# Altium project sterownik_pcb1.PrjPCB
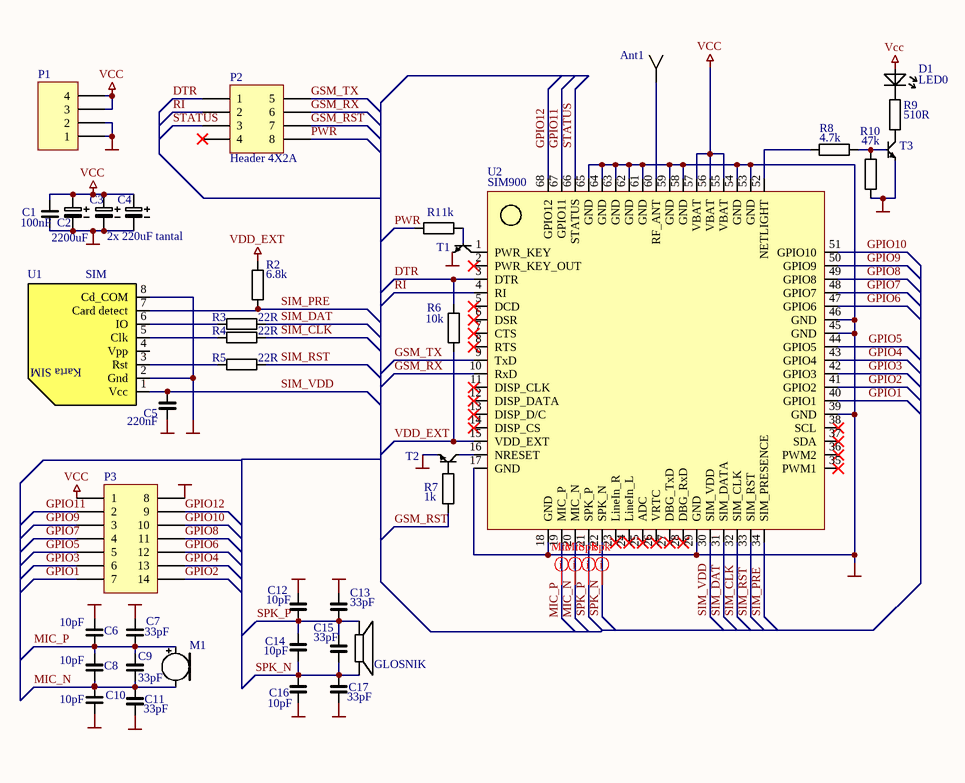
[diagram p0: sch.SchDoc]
1 sheet, 39 parts. Net scope: global (net labels, ports and power ports of the same name join across sheets).
Board file: modul_gsm.PcbDoc

## Sheet sch.SchDoc
size A4

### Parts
Ant1  Antena  [sma]  (value not drawn)
C1  100nF  [0805]
C2  2200uF  [CAPR5-4X5]
C3  2x 220uF tantal  [smd-d]
C4  CAP2  [smd-d]  (value not drawn)
C5  220nF  [0805]
C6  10pF  [0805]
C7  33pF  [0805]
C8  10pF  [0805]
C9  33pF  [0805]
C10  10pF  [0805]
C11  33pF  [0805]
C12  10pF  [0805]
C13  33pF  [0805]
C14  10pF  [0805]
C15  33pF  [0805]
C16  10pF  [0805]
C17  33pF  [0805]
D1  LED0  [led_0805]
M1  ELEKTRET  [ELEKTRET]  (value not drawn)
P1  Header 4  [HDR1X4]  (value not drawn)
P2  Header 4X2A  [HDR2X4_CEN]
P3  Header 7X2A  [HDR2X7_CEN]  (value not drawn)
R1  1k  [1206]
R2  6.8k  [1206]
R3  22R  [1206]
R4  22R  [1206]
R5  22R  [1206]
R6  10k  [1206]
R7  1k  [1206]
R8  4.7k  [1206]
R9  510R  [1206]
R10  47k  [1206]
T1  BC547B  [sot-23 rk]  (value not drawn)
T2  BC547B  [sot-23 rk]  (value not drawn)
T3  BC547B  [sot-23 rk]  (value not drawn)
U1  SIM  [simcard]
U2  SIM900  [SIM900]
  GLOSNIK  [hdr1x2]

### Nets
Gnd: Ant1.2 Ant1.3 Ant1.4 Ant1.5 C1.2 C2.2 C3.2 C4.2 C5.2 C6.1 C7.1 C10.2 C11.2 C12.1 C13.1 C16.2 C17.2 P1.1 P1.2 P3.8 R10.1(TOP) T1.1 T2.1 T3.1 U1.2(Gnd) U1.8(Cd_COM) U2.17(GND) U2.18(GND) U2.29(GND) U2.39(GND) U2.45(GND) U2.46(GND) U2.53(GND) U2.54(GND) U2.58(GND) U2.59(GND) U2.61(GND) U2.62(GND) U2.63(GND) U2.64(GND) U2.65(GND)
Vcc: C1.1 C2.1 C3.1 C4.1 D1.1(K) P1.3 P1.4 P3.1 U2.55(VBAT) U2.56(VBAT) U2.57(VBAT)
VDD_EXT: R2.1(TOP) R6.1(TOP) U2.15(VDD_EXT)
DTR: P2.1 R6.2(BOT) U2.3(DTR)
GPIO1: P3.7 U2.40(GPIO1)
GPIO2: P3.14 U2.41(GPIO2)
GPIO3: P3.6 U2.42(GPIO3)
GPIO4: P3.13 U2.43(GPIO4)
GPIO5: P3.5 U2.44(GPIO5)
GPIO6: P3.12 U2.47(GPIO6)
GPIO7: P3.4 U2.48(GPIO7)
GPIO8: P3.11 U2.49(GPIO8)
GPIO9: P3.3 U2.50(GPIO9)
GPIO10: P3.10 U2.51(GPIO10)
GPIO11: P3.2 U2.67(GPIO11)
GPIO12: P3.9 U2.68(GPIO12)
GSM_RST: P2.7 R7.2(BOT)
GSM_RX: P2.6 U2.10(RxD)
GSM_TX: P2.5 U2.9(TxD)
MIC_N: C8.2 C9.2 C10.1 C11.1 M1.2 U2.20(MIC_N)
MIC_P: C6.2 C7.2 C8.1 C9.1 M1.1 U2.19(MIC_P)
PWR: P2.8 R1.2(BOT)
RI: P2.2 U2.4(RI)
SIM_CLK: R4.1(TOP) U2.32(SIM_CLK)
SIM_DAT: R3.1(TOP) U2.31(SIM_DATA)
SIM_PRE: R2.2(BOT) U1.7(Card_detect) U2.34(SIM_PRESENCE)
SIM_RST: R5.1(TOP) U2.33(SIM_RST)
SIM_VDD: C5.1 U1.1(Vcc) U2.30(SIM_VDD)
SPK_N: C14.2 C15.2 C16.1 C17.1 U2.22(SPK_N) .2(B)
SPK_P: C12.2 C13.2 C14.1 C15.1 U2.21(SPK_P) .1(A)
STATUS: P2.3 U2.66(STATUS)
NetAnt1_1: Ant1.1 U2.60(RF_ANT)
NetD1_2: D1.2(A) R9.2(BOT)
NetR1_1: R1.1(TOP) T1.2
NetR3_2: R3.2(BOT) U1.6(IO)
NetR4_2: R4.2(BOT) U1.5(Clk)
NetR5_2: R5.2(BOT) U1.3(Rst)
NetR7_1: R7.1(TOP) T2.2
NetR8_1: R8.1(TOP) R10.2(BOT) T3.2
NetR8_2: R8.2(BOT) U2.52(NETLIGHT)
NetR9_1: R9.1(TOP) T3.3
NetT1_3: T1.3 U2.1(PWR_KEY)
NetT2_3: T2.3 U2.16(NRESET)

Not connected (* = marked no-connect by the designer): P2 4*; U1 4(Vpp); U2 2(PWR_KEY_OUT)* 5(DCD)* 6(DSR)* 7(CTS)* 8(RTS)* 11(DISP_CLK)* 12(DISP_DATA)* 13(DISP_D/C)* 14(DISP_CS)* 23(LineIn_R)* 24(LineIn_L)* 25(ADC)* 26(VRTC)* 27(DBG_TxD)* 28(DBG_RxD)* 35(PWM1)* 36(PWM2)* 37(SDA)* 38(SCL)*

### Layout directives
differential pair: MIC_N, MIC_P, SPK_N, SPK_P

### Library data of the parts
C1 C5-C17 = CAP: Condenstor
C2-C4 = CAP2: kONDENSATOR ELEKTROLITYCZNY
D1 = LED0: dioda elektroluminescencyjna LED
M1 = ELEKTRET: Mikrofon
P1 = Header 4: Header, 4-Pin
P2 = Header 4X2A: Header, 4-Pin, Dual row
P3 = Header 7X2A: Header, 7-Pin, Dual row
R1-R10 = RES: Rezystor
T1-T3 = BC547B: Tranzystor NPN
U1 = SIM_SLOT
